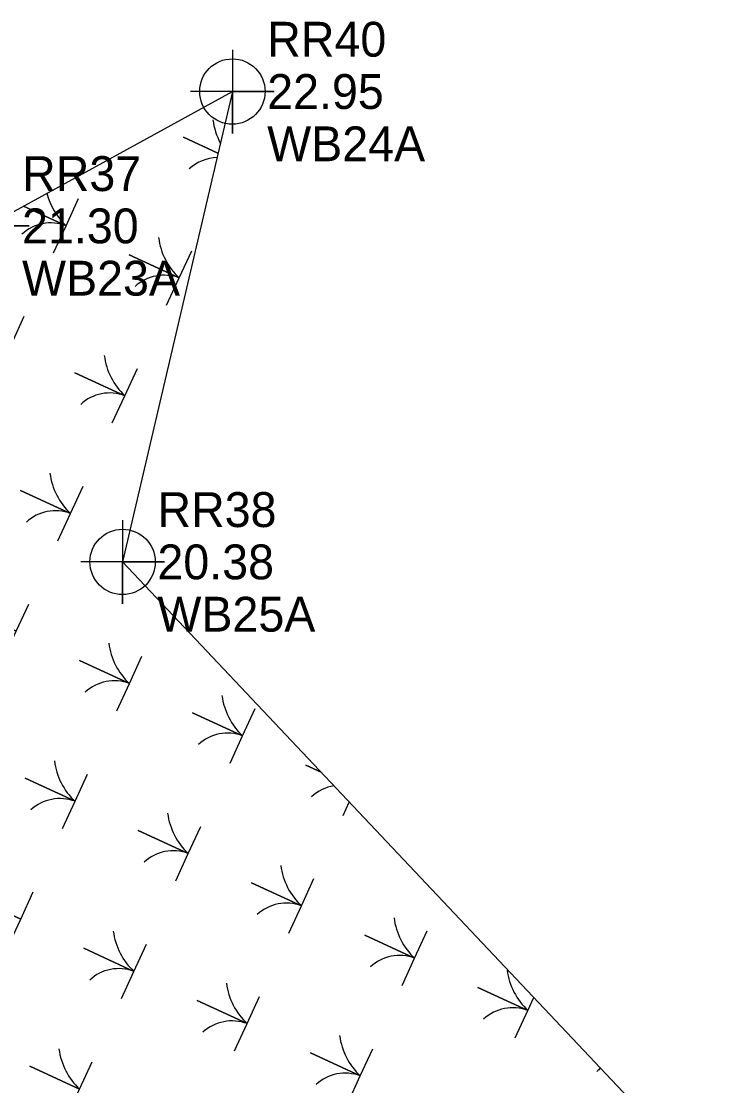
# Model space of a CAD drawing. Extents: x 2532037 to 2533565, y 713396 to 716867.
# Drawn here: x 2533041.8 to 2533092.2, y 715648.2 to 715724.5 of the extents above; entities that cross this region are included whole.
import ezdxf

# ---------------------------------------------------------------- set-up
doc = ezdxf.new("R2010")
doc.units = 0
for name, color, linetype in [('Exist Environmental Wetland Boundary', 7, 'Continuous'), ('Exist Environmental Wetland Boundary Cogo Comment', 7, 'Continuous'), ('Exist Environmental Wetland Boundary Cogo Elevation', 7, 'Continuous'), ('Exist Environmental Wetland Boundary Cogo Number', 7, 'Continuous'), ('Exist Environmental Wetland Boundary Cogo Point CELL', 7, 'Continuous'), ('Scratch_Level_1', 7, 'Continuous')]:
    doc.layers.add(name, color=color, linetype=linetype)

msp = doc.modelspace()

# ---------------------------------------------------------------- linework, layer by layer
at = {"layer": 'Exist Environmental Wetland Boundary'}
for p, q in [((2533039.336, 715709.834), (2533056.925, 715719.469)), ((2533056.925, 715719.469), (2533049.048, 715685.741)), ((2533049.048, 715685.741), (2533092.183, 715640.093))]:
    msp.add_line(p, q, dxfattribs=at)
at = {"layer": 'Exist Environmental Wetland Boundary Cogo Point CELL'}
for points in [[(2533056.925, 715722.469), (2533056.925, 715716.469), (2533056.925, 715719.469), (2533059.925, 715719.469), (2533053.925, 715719.469)], [(2533039.336, 715712.834), (2533039.336, 715706.834), (2533039.336, 715709.834), (2533042.336, 715709.834), (2533036.336, 715709.834)], [(2533049.048, 715688.741), (2533049.048, 715682.741), (2533049.048, 715685.741), (2533052.048, 715685.741), (2533046.048, 715685.741)]]:
    msp.add_lwpolyline(points, dxfattribs=at)
for centre in [(2533056.925, 715719.469), (2533049.048, 715685.741)]:
    msp.add_circle(centre, 2.344, dxfattribs=at)
at = {"layer": 'Scratch_Level_1'}
msp.add_line((2533064.879, 715667.567), (2533065.319, 715668.522), dxfattribs=at)
for points in [[(2533055.895, 715715.06), (2533053.428, 715716.199), (2533055.895, 715715.06)], [(2533041.938, 715711.259), (2533044.99, 715709.85), (2533045.891, 715711.803)], [(2533044.089, 715707.898), (2533044.99, 715709.85), (2533041.938, 715711.259)], [(2533052.21, 715704.149), (2533053.111, 715706.101), (2533049.53, 715707.755), (2533053.111, 715706.101), (2533054.013, 715708.053)], [(2533040.19, 715699.454), (2533041.091, 715701.406), (2533037.51, 715703.06), (2533041.091, 715701.406), (2533041.993, 715703.358)], [(2533048.312, 715695.704), (2533049.213, 715697.657), (2533045.631, 715699.31), (2533049.213, 715697.657), (2533050.114, 715699.609)], [(2533044.413, 715687.26), (2533045.314, 715689.212), (2533041.733, 715690.866), (2533045.314, 715689.212), (2533046.216, 715691.165)], [(2533040.515, 715678.815), (2533041.416, 715680.768), (2533037.834, 715682.421), (2533041.416, 715680.768), (2533042.317, 715682.72)], [(2533048.636, 715675.066), (2533049.537, 715677.018), (2533045.956, 715678.672), (2533049.537, 715677.018), (2533050.439, 715678.971)], [(2533056.758, 715671.317), (2533057.659, 715673.269), (2533054.077, 715674.923), (2533057.659, 715673.269), (2533058.56, 715675.222)], [(2533063.29, 715670.67), (2533062.198, 715671.173), (2533063.29, 715670.67)], [(2533044.738, 715666.622), (2533045.639, 715668.574), (2533042.057, 715670.228), (2533045.639, 715668.574), (2533046.54, 715670.527)], [(2533052.859, 715662.872), (2533053.76, 715664.825), (2533050.179, 715666.478), (2533053.76, 715664.825), (2533054.662, 715666.777)], [(2533060.981, 715659.123), (2533061.882, 715661.075), (2533058.3, 715662.729), (2533061.882, 715661.075), (2533062.783, 715663.028)], [(2533040.839, 715658.177), (2533041.741, 715660.13), (2533038.159, 715661.783), (2533041.741, 715660.13), (2533042.642, 715662.082)], [(2533069.102, 715655.374), (2533070.003, 715657.326), (2533066.421, 715658.98), (2533070.003, 715657.326), (2533070.905, 715659.278)], [(2533048.961, 715654.428), (2533049.862, 715656.38), (2533046.28, 715658.034), (2533049.862, 715656.38), (2533050.763, 715658.333)], [(2533077.223, 715651.624), (2533078.125, 715653.577), (2533074.543, 715655.23), (2533078.125, 715653.577), (2533078.557, 715654.513)], [(2533057.082, 715650.679), (2533057.983, 715652.631), (2533054.402, 715654.285), (2533057.983, 715652.631), (2533058.885, 715654.583)], [(2533065.204, 715646.929), (2533066.105, 715648.882), (2533062.523, 715650.535), (2533066.105, 715648.882), (2533067.006, 715650.834)], [(2533045.062, 715645.984), (2533045.964, 715647.936), (2533042.382, 715649.59), (2533045.964, 715647.936), (2533046.865, 715649.888)]]:
    msp.add_lwpolyline(points, dxfattribs=at)
for centre, radius, start, end in [((2533060.297, 715718.051), 4.806, 187.34643, 208.22962), ((2533055.926, 715711.668), 3.075, 91.96131, 132.75394), ((2533048.277, 715713.356), 4.806, 194.16985, 226.84116), ((2533043.906, 715706.973), 3.075, 69.35932, 132.75394), ((2533056.399, 715709.606), 4.806, 187.34643, 226.84116), ((2533052.028, 715703.224), 3.075, 69.35932, 132.75394), ((2533052.5, 715701.162), 4.806, 187.34643, 226.84116), ((2533048.129, 715694.779), 3.075, 69.35932, 132.75394), ((2533048.602, 715692.718), 4.806, 187.34643, 226.84116), ((2533044.231, 715686.335), 3.075, 69.35932, 132.75394), ((2533052.825, 715680.524), 4.806, 187.34643, 226.84116), ((2533048.454, 715674.141), 3.075, 69.35932, 132.75394), ((2533060.946, 715676.775), 4.806, 187.34643, 226.84116), ((2533056.575, 715670.392), 3.075, 69.35932, 132.75394), ((2533048.926, 715672.08), 4.806, 187.34643, 226.84116), ((2533064.697, 715666.643), 3.075, 98.83605, 132.75394), ((2533044.555, 715665.697), 3.075, 69.35932, 132.75394), ((2533057.048, 715668.33), 4.806, 187.34643, 226.84116), ((2533052.677, 715661.948), 3.075, 69.35932, 132.75394), ((2533065.169, 715664.581), 4.806, 187.34643, 226.84116), ((2533060.798, 715658.198), 3.075, 69.35932, 132.75394), ((2533073.291, 715660.832), 4.806, 187.34643, 226.84116), ((2533053.149, 715659.886), 4.806, 187.34643, 226.84116), ((2533068.92, 715654.449), 3.075, 69.35932, 132.75394), ((2533048.778, 715653.503), 3.075, 69.35932, 132.75394), ((2533081.412, 715657.082), 4.806, 187.34643, 226.84116), ((2533061.271, 715656.137), 4.806, 187.34643, 226.84116), ((2533077.041, 715650.699), 3.075, 69.35932, 132.75394), ((2533056.9, 715649.754), 3.075, 69.35932, 132.75394), ((2533069.392, 715652.387), 4.806, 187.34643, 226.84116), ((2533049.251, 715651.442), 4.806, 187.34643, 226.84116), ((2533065.021, 715646.004), 3.075, 69.35932, 132.75394), ((2533085.162, 715646.95), 3.075, 126.02997, 132.75394)]:
    msp.add_arc(centre, radius, start, end, dxfattribs=at)

# ---------------------------------------------------------------- texts
at = {"layer": 'Exist Environmental Wetland Boundary Cogo Comment'}
for s, p in [('WB24A', (2533059.425, 715714.469)), ('WB23A', (2533041.836, 715704.834)), ('WB25A', (2533051.548, 715680.741))]:
    msp.add_text(s, height=2.5, dxfattribs=at).set_placement(p)
at = {"layer": 'Exist Environmental Wetland Boundary Cogo Elevation'}
for s, p in [('22.95', (2533059.425, 715718.219)), ('21.30', (2533041.836, 715708.584)), ('20.38', (2533051.548, 715684.491))]:
    msp.add_text(s, height=2.5, dxfattribs=at).set_placement(p)
at = {"layer": 'Exist Environmental Wetland Boundary Cogo Number'}
for s, p in [('RR40', (2533059.425, 715721.969)), ('RR37', (2533041.836, 715712.334)), ('RR38', (2533051.548, 715688.241))]:
    msp.add_text(s, height=2.5, dxfattribs=at).set_placement(p)

doc.saveas('drawing.dxf')
